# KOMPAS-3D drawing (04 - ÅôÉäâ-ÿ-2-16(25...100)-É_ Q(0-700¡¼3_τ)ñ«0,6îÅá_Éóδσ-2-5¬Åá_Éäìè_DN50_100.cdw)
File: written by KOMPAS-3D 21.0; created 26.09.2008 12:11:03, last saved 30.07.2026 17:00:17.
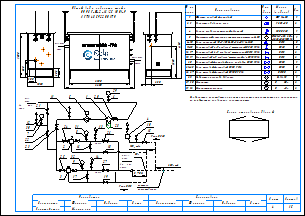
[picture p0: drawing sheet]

Sheets 1-2: A3, landscape

Document properties: Наименование: Макро:21; Автор: RaskoAdmin; Форматы листов документа: 2xA3; Полное имя файла: \\UR38nt01\Departments\КТО\КБ ПУРДГ\Заявки\Прайс-лист на типовые шкафы ГРПШ\ПУРДГ_стандарт_30_04_2026\ПУРДГ с РДНК\ПУРДГ-Ш-2-16(25...100)-Р_ Q(0-700нм3_ч)до0,6МПа_Рвых-2-5кПа_РДНК_DN50_100.cdw

Title block, sheet 1: Наименование: Пункт учета газа / ПУГ-Ш-400-Р / ЛГТИ.485922.001ТУ; designation: ЛГТИ.03.4411141; sheet number: 1; Количество листов документа: 2; organisation: ООО "ЭЛЬСТЕР Газэлектроника"; Форматы листов документа: A3; stored path: C:\Рабочие документы\Компас\ПУГ\Схема.cdw; Разработал: Устинов; Проверил: Кошкин; Утвердил: Кошкин
Title block, sheet 2: sheet number: 2; stored path: D:\Рабочие документы\Заявки\ПУРДГ\ПУРДГ-ШУЭО-2-100-Р 4411220.cdw; designation, second copy: ЛГТИ.03.4411141-

Views: Вид 1, Вид 2
Referenced files: wcvoit.frw
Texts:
  Normal
  № на
  схеме
  Усл.
  обозн.
  Марка
  (модель)
  Кол.
  Фильтр газовый фланцевый
  ФГ 16-50
  Регулятор давления газа
  РДНК-50
  Клапан предохранительный сбросной
  КПС DN20
  Измерительный комплекс с ротационным счетчиком Ду50
  СГ-ЭК-Р-(0,2...2,0)-
  Кран кнопочный VE-РАСКО-НЗ-1,6-G1/2-М20
  DN15
  Кран шаровой "под приварку" штуцерный DN20 PN16
  DN20
  Кран шаровой "под приварку" штуцерный DN15 PN16
  Кран шаровой "под приварку" штуцерный п/п DN15 PN16
  Кран шаровой фланцевый с мех. приводом DN50 PN16
  Кран шаровой фланцевый DN50 PN16
  Кран шаровой фланцевый DN100 PN16
  DN50
  DN100
  Индикатор перепада давления
  Манометр
  Манометр-напоромер
  Delta 15
  0...     МПа
  0...     кПа
  Общий вид и габариты шкафа
  ПУРДГ-Ш-2-16(25...100)-Р
  Выход газа
  Вход газа
  logo-rasko-ge.png
  DN 1
  местное
  сопротивление
  Римп DN15
  Римп DN20
  Выход
  газа
  Р=     кПа
  Вход
  Р=       МПа
  PDI
  Схема открывания дверей
  Предприятие изготовитель может заменять комплектующие на аналогичные,
  не ухудшающие заявленных характеристик.
  Должность
  Конструктор
  Фамилия
  Подпись
  Дата
  Согласовано
  Максимкин
  Лист
  Листов
  POLYLINE_STYLE_0.18_RGB_0_0_0
  POLYLINE_STYLE_0.50_RGB_0_0_0
  POLYLINE_STYLE_0.34_RGB_0_0_0
  PHANTOM_RGB_0_0_0_SC_1_THICK_0.18
  K5LT_THIN_RGB_0_0_0_THICK_0.18
  K5LT32769_RGB_0_0_0_THICK_0.18
  K5LT12_RGB_0_0_0_SC_1_THICK_0.18
  K5LT_DASHED_RGB_0_0_0_SC_1_THICK_0.18
  ACISOTGL_RGB_0_0_0_SC_0.8_THICK_0.25
  CONTINUOUS_RGB_0_127_31_THICK_0.3
  CONTINUOUS_RGB_0_0_255_THICK_0.35
  CONTINUOUS_RGB_255_0_0_THICK_0.35
  POLYLINE_STYLE_0.25_RGB_0_0_0
  CONTINUOUS_RGB_0_0_0_THICK_0.5
  POLYLINE_STYLE_0.35_RGB_0_0_255
  CONTINUOUS_RGB_0_0_0_THICK_0.4
  CONTINUOUS_RGB_0_0_0_THICK_0.35
  НЕВИДИМАЯ_RGB_0_0_0_SC_0.3_THICK_0.25
  СONTINUOUS_RGB_0_0_0_THICK_0.25
  ОСЕВАЯ2_RGB_248_153_30_SC_0.3_THICK_0.25
  Без оформления
Dimensions and other numbers on the sheet: 1; 2, 3; 2; 4; 5; 6-10; 11-15; 16, 17; 18, 19; 20; 21-25; 26, 27; 28; 29, 30; 31, 32; 1500; 250; 300; 1050; 550; 305; 2300; 4130; 2000; 2600; 5,,,7DN 1; 7; 30; 12; 21; 22; 23; 11; 6; 29; 24; 31; 8; 16; 13; 26; 18; 10; 15; 25; 32; 9; 3; 17; 14; 27; 19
